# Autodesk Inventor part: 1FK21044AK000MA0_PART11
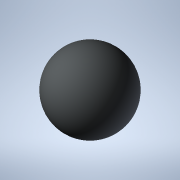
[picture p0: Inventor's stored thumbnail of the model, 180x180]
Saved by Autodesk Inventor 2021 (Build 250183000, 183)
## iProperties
Created: 2025-04
Part Number: 1FK21044AK000MA0_PART11
Material: Generic
Catalog Web Link: www.3dfindit.com
Description: -Servo synchronous motor
Document SubType Name: Modeling
Designer: psAdmin
Mass: 0.137258 g
Surface Area: 1.2868 cm^2
Volume: 0.137258 cm^3
Density: 1 g/cm^3
Appearance: PSOLRGB-212-217-219
Category: PARTsolutions
Title: 1FK21044AK000MA0_PART11
Author: Cadenas PARTsolutions
Comments: Servo synchronous motor
Sending System: PARTsolutions
Preprocessor: ST-DEVELOPER v19.3
PSOL_IDENT_0: {$CADENAS_DATA/23d-libs/siemens_ag/_cat_/87/f4/1fk21044ak000ma0.prj},216 {VTYP=3D},{NB=1FK21044AK000
PSOL_IDENT_1: MA0_PART11},{LINA=1FK21044AK000MA0_PART11},{NN=1FK21044AK000MA0_PART11},{NOPRJ=TRUE},{DATE=19.08.202
PSOL_IDENT_2: 5 14:00:48},{GEOMDATE=30.07.2025 02:00:50},{VERSION=},{LINEID=10},{WBVAR=},{WBNUMERIC=}  {NB=1FK2104
PSOL_IDENT_3: 4AK000MA0_PART11},{LINA=1FK21044AK000MA0_PART11},{KT=DUMMY},{PREVIEW=../../../_pool_/cb/72/p_d211_xx
PSOL_IDENT_4: _00434j.png},{DESCSHORT=SIMOTICS S-1FK2 HD, SINAMICS S210 3AC 400V-480V, 0.95 Nm, 6000 rpm},{DESCLON
PSOL_IDENT_5: G=SIMOTICS S-1FK2 HD servo motor M0=1.27 Nm; PN = 0.6 kW at nN=6000 rpm (380-480 V); PN = 0.4 kW at
PSOL_IDENT_6: nN=3000 rpm (200-240 V); degree of protection IP64; cylindrical shaft D19x40mm; absolute encoder 22-
PSOL_IDENT_7: bit + 12-bit multiturn (encoder AM22DQC); with OCC interface; plug size M17, rotatable; SIMOTICS S-1
PSOL_IDENT_8: FK2 servomotorfor a wide range of uses in industrial environments. SIMOTICS S‑1FK2 servomotors are c
PSOL_IDENT_9: ompact synchronous motors with a high dynamic performance that set themselves apart as a result of t
PSOL_IDENT_10: heir high power density, degree of protection and overload capability. The motors are available in t
PSOL_IDENT_11: wo variants: as High Dynamic variant (highest dynamic performance as a result of the low intrinsic m
PSOL_IDENT_12: oment of inertia for applications demanding a high dynamic performance with low moved masses) - and
PSOL_IDENT_13: as Compact variant (precise and stable closed-loop control for medium up to large moved masses as a
PSOL_IDENT_14: result of a medium intrinsic moment of inertia). SIMOTICSS‑1FK2 servomotors fully exploit their stre
PSOL_IDENT_15: ngths in a system with the SINAMICSS210 frequency converter and simple connection using the one cabl
PSOL_IDENT_16: e connection (OCC). Advantages include the short control and positioning times, fast and precise cor
PSOL_IDENT_17: rection of disturbing quantities as well as stable control with a high dynamic performance. The serv
PSOL_IDENT_18: o motors can be configured to address a wide range of requirements. For example with and without hol
PSOL_IDENT_19: ding brake, IP64 or IP65 degree of protection, singleturn or multiturn absolute encoders - to name j
PSOL_IDENT_20: ust a few. Further, the servomotors are available in different shaft heights extending from 20 to 10
PSOL_IDENT_21: 0. A shaft sealing ring is available to achieve an IP65 degree of protection and for subsequent moun
PSOL_IDENT_22: ting at the motor or as spare part. SIMOTICS - the optimum motor for each and every motion control a
PSOL_IDENT_23: pplication.},{INTNO=195125056312},{SUPPLIERALTNO=1FK2104-4AK00-0MA0},{MANUID=1FK21044AK000MA0},{MANU
PSOL_IDENT_24: NAME=Siemens},{MANUTYPEDESC=Synchronous motor 1FK2-HD 1,27 Nm},{AAU732=SIMOTICS},{AAO057=S-1FK2},{AA
PSOL_IDENT_25: U734=SIMOTICS S-1FK2 HD servo motor M0=1.27 Nm; PN = 0.6 kW at nN=6000 rpm (380-480 V); PN = 0.4 kW
PSOL_IDENT_26: at nN=3000 rpm (200-240 V); degree of protection IP64; cylindrical shaft D19x40mm; absolute encoder
PSOL_IDENT_27: 22-bit + 12-bit multiturn (encoder AM22DQC); with OCC interface; plug size M17, rotatable;},{AAW338=
PSOL_IDENT_28: Synchronous motor 1FK2-HD 1,27 Nm},{AAO742=SIMOTICS},{AAO663=4042948690994},{NOCUPEROU=1},{PRICEQUAN
PSOL_IDENT_29: TITY=1},{QUANTITYMIN=1},{QUANTITYINT=1},{CTN=85015100},{COO=DE},{AAO676=1FK2104-4AK00-0MA0},{AAO677=
PSOL_IDENT_30: Siemens AG},{ORDERUNIT=C62},{CONTENTUNIT=C62}
NB: 1FK21044AK000MA0_PART11
NT: Servo synchronous motor
NBSYN: $MANUID._PART11
LINA: 1FK21044AK000MA0_PART11
CATALOG: SIEMENS
PREVIEW: ../../../_pool_/cb/72/p_d211_xx_00434j.png
DESCSHORT: SIMOTICS S-1FK2 HD, SINAMICS S210 3AC 400V-480V, 0.95 Nm, 6000 rpm
DESCLONG: SIMOTICS S-1FK2 HD servo motor M0=1.27 Nm; PN = 0.6 kW at nN=6000 rpm (380-480 V); PN = 0.4 kW at nN=3000 rpm (200-240 V); degree of protection IP64; cylindrica
INTNO: 195125056312
SUPPLIERALTNO: 1FK2104-4AK00-0MA0
MANUID: 1FK21044AK000MA0
MANUNAME: Siemens
MANUTYPEDESC: Synchronous motor 1FK2-HD 1,27 Nm
AAU732: SIMOTICS
AAO057: S-1FK2
AAU734: SIMOTICS S-1FK2 HD servo motor M0=1.27 Nm; PN = 0.6 kW at nN=6000 rpm (380-480 V); PN = 0.4 kW at nN=3000 rpm (200-240 V); degree of protection IP64; cylindrica
AAW338: Synchronous motor 1FK2-HD 1,27 Nm
AAO742: SIMOTICS
AAO663: 4042948690994.0
NOCUPEROU: 1
PRICEQUANTITY: 1
QUANTITYMIN: 1
QUANTITYINT: 1
CTN: 85015100
COO: DE
ARTICLENO: 1FK21044AK000MA0_PART11
BOMINFO: 1FK21044AK000MA0_PART11
CREATOR: CADENAS GmbH
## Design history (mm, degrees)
feature "2025_04_17_15_37_40_0588"
body "Solid1"
